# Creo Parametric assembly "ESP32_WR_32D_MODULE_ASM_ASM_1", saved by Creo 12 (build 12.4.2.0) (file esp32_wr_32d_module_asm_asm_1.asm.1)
Units: Custom; MM, KILOGRAM, SECS

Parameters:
  PTC_WM_ITERATION = "0"
  PTC_WM_VERSION = "-.0"
  PTC_WM_LIFECYCLE_STATE = "In Work"
  PTC_WM_LIFECYCLE = "MO_CADDocument"
  PTC_WM_CREATED_BY = "Maximilian Roepper (Z0017RMS: MO)"
  PTC_WM_CREATED_ON = "18-Sep-26 11:36:42 AM"
  PTC_WM_MODIFIED_BY = "Maximilian Roepper (Z0017RMS: MO)"
  PTC_WM_MODIFIED_ON = "18-Sep-26 11:36:46 AM"
  PDMLINKNUMBER = "PDM000071455093"
  PTC_WM_NUMBER = "PDM000071455093"

Other parameters: WEIGHT, WEIGHT_FACTOR, WEIGHT_ADD, MC_ERRORS, SUPPLIER

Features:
  1. coordinate system
  2. imported feature
  3. component "PCB_MINCE_PRT_1"
  4. component "BOX_PRT_1"
  5. component "TEXT_ESP045_ASM_ASM_1"
  6. component "TEXT_ESPRESSIF009_ASM_ASM_1"
  7. component "PINS_H_ASM_ASM_1"
  8. component "PINS_LEFT_ASM_ASM_1"
  9. component "PINS_RIGHT_ASM_ASM_1"

Other named items: DRW_VIEW_ORG, ROUGH-GROB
